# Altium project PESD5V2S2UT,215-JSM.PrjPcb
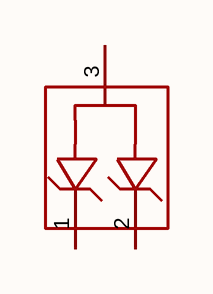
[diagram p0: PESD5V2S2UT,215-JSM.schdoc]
1 sheet, 1 parts. Net scope: global (net labels, ports and power ports of the same name join across sheets).

## Sheet PESD5V2S2UT,215-JSM.schdoc
size 127 x 101 mm

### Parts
D?  pesd5v2s2ut,215-jsm  [SOT-23-3_L2.9-W1.3-P1.90-LS2.4-BR]  (value not drawn)

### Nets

Not connected (* = marked no-connect by the designer): D? 1 2 3

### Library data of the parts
D? = pesd5v2s2ut,215-jsm: 极性:单向;反向截止电压(Vrwm):5V;钳位电压:20V;峰值脉冲电流(Ipp):13A@8/20us;峰值脉冲功率(Ppp):260W@8/20us;击穿电压(VBR):6V;; Manufacturer: JSMSEMI(杰盛微); AddInBom: yes; ModelId: c62791f0466c4ae2a892c056b845b0ca; ModelName: SOT-23-3P_L2.9-W1.3-H1.0-LS2.4-P0.95; ModelTransform: 98.425,114.173,0,180,0,0,0.0005,-0.0005,0; Polarity: 单向; Reverse Stand-Off Voltage (Vrwm): 5V; Clamping Voltage: 20V; Voltage - Breakdown: 6V; Reverse Leakage Current (Ir): 5uA; level of protection: IEC 61000-4-5；IEC 61000-4-2; Type: ESD; Junction Capacitance: 200pF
